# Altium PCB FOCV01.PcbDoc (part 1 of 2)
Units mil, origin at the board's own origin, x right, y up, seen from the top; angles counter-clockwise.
Board outline 3845.03 x 2425.03 mil, 2 copper layers (Top Layer, Bottom Layer); 118 components, 90 nets, 380 pads, 232 vias.
Unrouted connection lines stored in the file: 2.
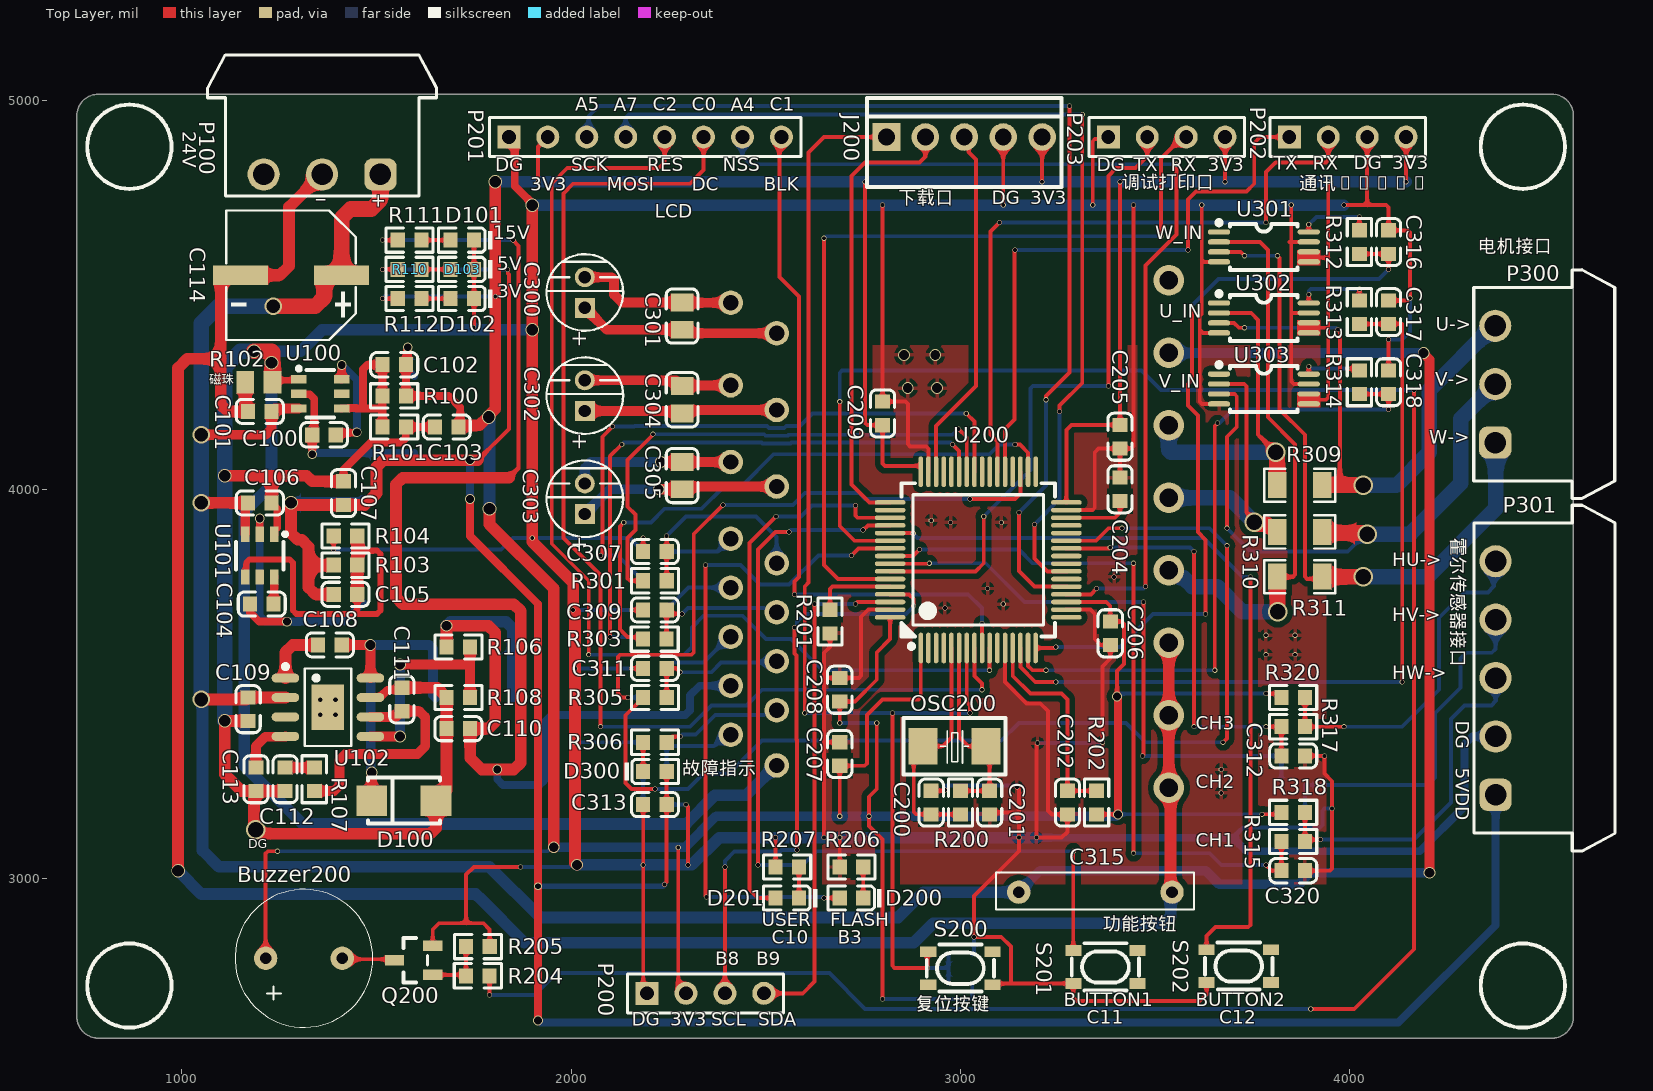
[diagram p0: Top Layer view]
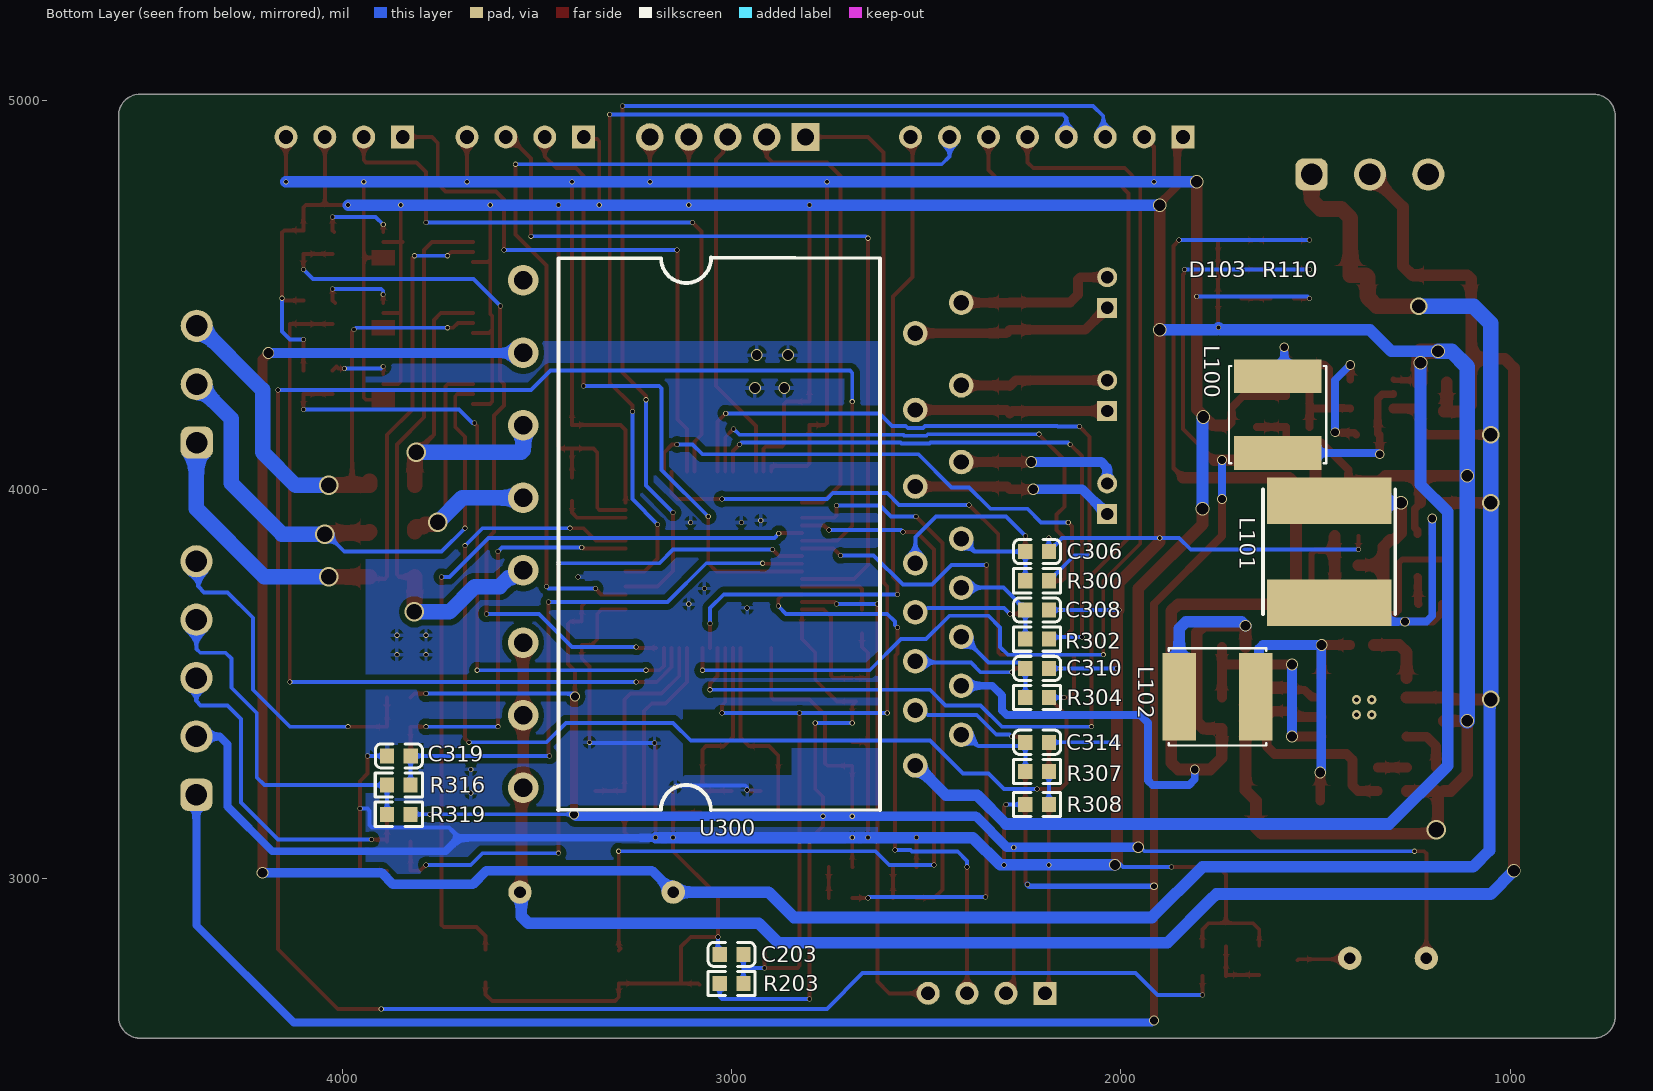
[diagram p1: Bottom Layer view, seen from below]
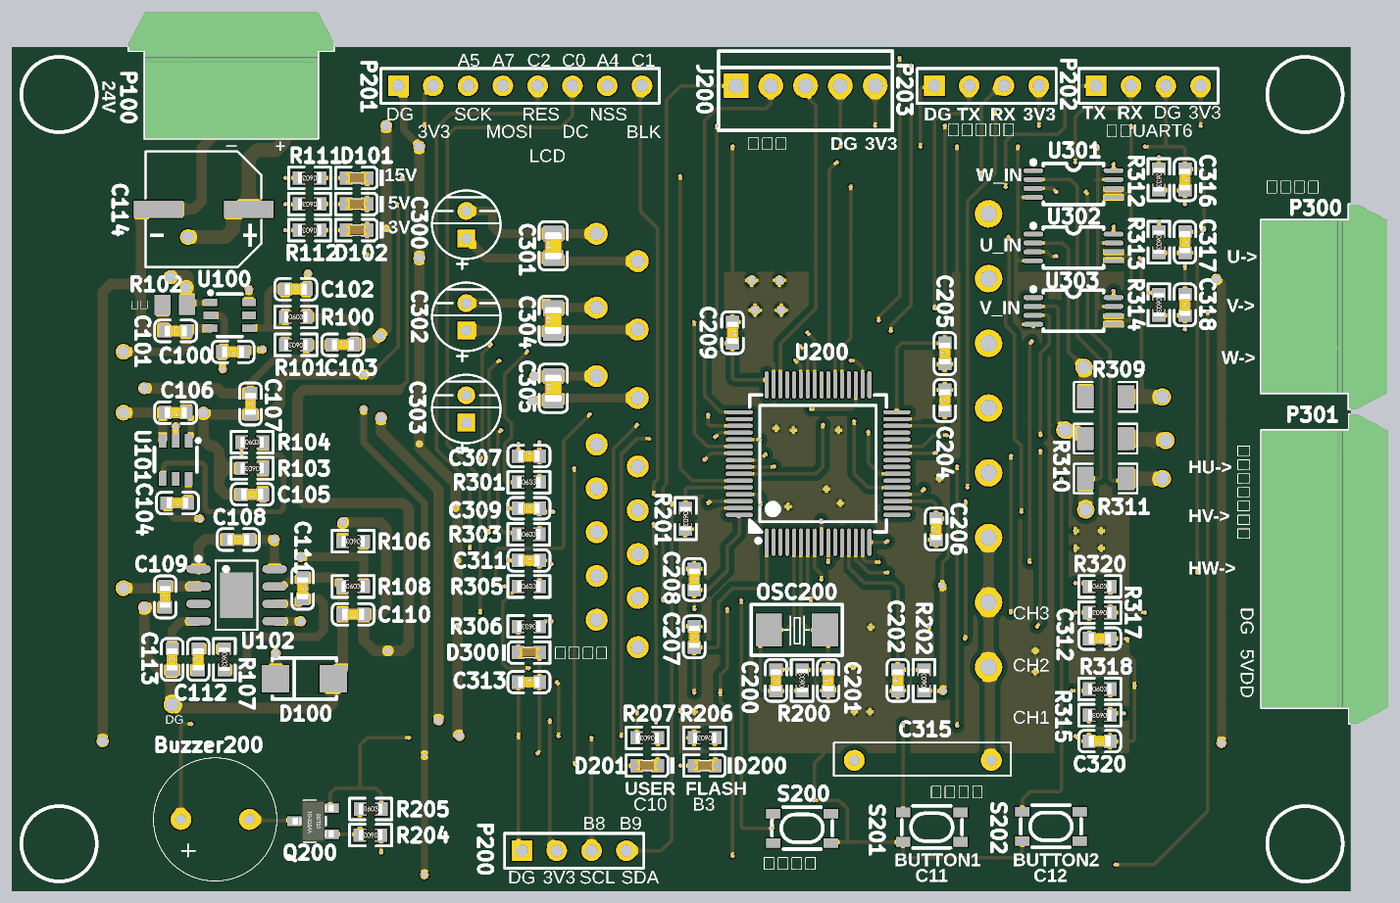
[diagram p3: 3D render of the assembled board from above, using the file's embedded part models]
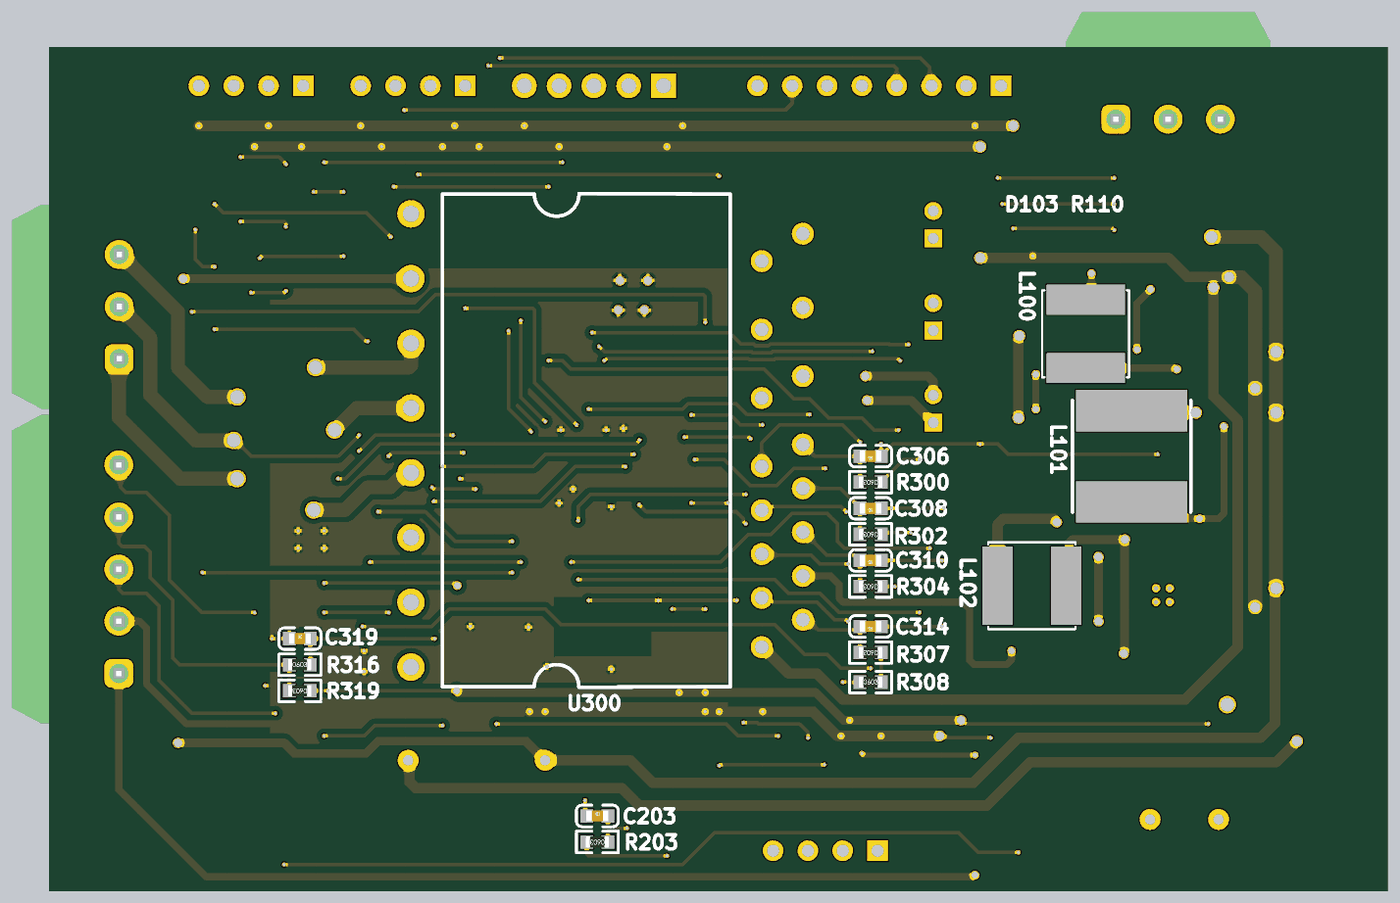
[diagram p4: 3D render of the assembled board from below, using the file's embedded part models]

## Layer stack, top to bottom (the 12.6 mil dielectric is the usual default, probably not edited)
Top Solder: solder mask 0.4, Solder Resist, Dk 3.5
Top Layer: signal copper 1.4
Dielectric 1: dielectric 12.6, FR-4, Dk 4.8
Bottom Layer: signal copper 1.4
Bottom Solder: solder mask 0.4, Solder Resist, Dk 3.5

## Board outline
777.9,2590.44 cw(c785,2645) 730.44,2637.9 cw(c735,2640) 729.98,2640 729.99,4960 cw(c785,4960) 784.97,5015.01 cw(c785,5010) 785,5015.01 4520,5015.02 cw(c4520,4960) 4575.02,4960 cw(c4570,4960) 4575.01,4959.97 4575.01,2645 4575.02,2645 ccw(c4570,2645) 4575.01,2645.03 4575.02,2645 cw(c4520,2645) 4527.1,2590.44 cw(c4525,2595) 4525,2589.99 4520,2589.99 ccw(c4520,2595) 4520,2589.99 ccw(c4520,2645) 4520.01,2589.99 4520,2589.99 785.08,2589.99 cw(c785,2595) 785,2589.98 cw(c785,2645) 784.72,2589.99 780,2589.99 cw(c780,2595)

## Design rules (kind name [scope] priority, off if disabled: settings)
Clearance [All] p1: gap=6 ignorepadtopadclearanceinfootprint=FALSE
HoleToHoleClearance [All] p1: gap=0 allowstackedmicrovias=TRUE
MinimumSolderMaskSliver [All] p1: minsoldermaskwidth=0
PolygonConnect [All] p1: connectstyle=Relief reliefconductorwidth=10 reliefentries=4 polygonreliefangle="90 Angle" airgapwidth=10
RoutingVias [All] p1: holewidth=28 width=50 viastyle="Through Hole" minholewidth=28 minwidth=50 maxholewidth=28 maxwidth=50
SilkToSilkClearance [All] p1: silktosilkclearance=0
SilkToSolderMaskClearance [IsPad] p1: minsilkscreentomaskgap=0 clearancetoexposedcopper=TRUE
SolderMaskExpansion [All] p1: expansion=4 istentingtop=FALSE
Width [All] p1: maxlimit=100 minlimit=10 preferedwidth=10
26 further rules are at their usual default settings.

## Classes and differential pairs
component class 03_Sensor: C300 C301 C302 C303 C304 C305 C306 C307 C308 C309 C310 C311 C312 C313 C314 C315 C316 C317 C318 C319 C320 D300 P300 P301 R300 R301 R302 R303 R304 R305 R306 R307 R308 R309 R310 R311 R312 R313 R314 R315 R316 R317 R318 R319 R320 U300 U301 U302 U303
component class 02_Mcu: Buzzer200 C200 C201 C202 C203 C204 C205 C206 C207 C208 C209 D200 D201 J200 OSC200 P200 P201 P202 P203 Q200 R200 R201 R202 R203 R204 R205 R206 R207 S200 S201 S202 U200
component class 01_Power: C100 C101 C102 C103 C104 C105 C106 C107 C108 C109 C110 C111 C112 C113 C114 D100 D101 D102 D103 L100 L101 L102 P100 R100 R101 R102 R103 R104 R106 R107 R108 R110 R111 R112 U100 U101 U102

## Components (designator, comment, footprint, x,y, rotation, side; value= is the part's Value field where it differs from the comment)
Buzzer200 "Buzzer" buzzer-0905 1313.43,2795 r90 top
C100 "100nF (104) 10% 50V" 0603_C 1365,4140 r180 top
C101 "10uF (106) 10% 50V" 0603_C 1200,4200 r0 top
C102 "56pF (560) 5% 50V" 0603_C 1545.32,4320 r0 top
C103 "22uF (226) 20% 6.3V" 0603_C 1680.32,4160 r0 top
C104 "100nF (104) 10% 50V" 0603_C 1205,3705 r180 top
C105 "56pF (560) 5% 50V" 0603_C 1420,3730 r180 top
C106 "10uF (106) 10% 50V" 0603_C 1200,3965 r180 top
C107 "22uF (226) 20% 6.3V" 0603_C 1415,3990 r270 top
C108 "100nF (104) 10% 50V" 0603_C 1380,3600 r0 top
C109 "10uF (106) 10% 50V" 0603_C 1170,3435 r90 top
C110 "10uF (106) 10% 10V" 0603_C 1710,3385 r180 top
C111 "10pF (100) 5% 50V" 0603_C 1565,3460 r270 top
C112 "1.5pF (1R5) 0.25pF 50V" 0603_C 1265,3255 r90 top
C113 "8.2nF (822) 10% 50V" 0603_C 1190,3255 r90 top
C114 "220UF/35V" CAP_L8.3_W8.3 1280,4550 r180 top
C200 "22pF (220) 5% 50V" 0603_C 2925,3195 r270 top
C201 "22pF (220) 5% 50V" 0603_C 3075,3195 r90 top
C202 "100nF (104) 10% 50V" 0603_C 3275,3195 r90 top
C203 "100nF (104) 10% 50V" 0603_C 3000,2805 r180 bottom
C204 "2.2uF (225) 10% 16V" 0603_C 3410,4000 r90 top
C205 "100nF (104) 10% 50V" LC-0603_C 3410,4135 r90 top
C206 "100nF (104) 10% 50V" LC-0603_C 3385,3630 r90 top
C207 "100nF (104) 10% 50V" LC-0603_C 2690,3320 r270 top
C208 "100nF (104) 10% 50V" LC-0603_C 2690,3485 r270 top
C209 "100nF (104) 10% 50V" LC-0603_C 2800,4195 r270 top
C300 "22UF/35V" 电解电容5*7 2010.03,4500.33 r90 top
C301 "100nF(104) 10% 50V" 0805_C 2285,4445 r90 top
C302 "22UF/35V" 电解电容5*7 2010.03,4235.33 r90 top
C303 "22UF/35V" 电解电容5*7 2010.03,3970.33 r90 top
C304 "100nF(104) 10% 50V" 0805_C 2285,4230 r90 top
C305 "100nF(104) 10% 50V" 0805_C 2285,4035 r90 top
C306 "1nF (102) 10% 50V" 0603_C 2215,3840 r0 bottom
C307 "1nF (102) 10% 50V" 0603_C 2215,3840 r0 top
C308 "1nF (102) 10% 50V" 0603_C 2215,3690 r0 bottom
C309 "1nF (102) 10% 50V" 0603_C 2215,3690 r0 top
C310 "1nF (102) 10% 50V" 0603_C 2215,3540 r0 bottom
C311 "1nF (102) 10% 50V" 0603_C 2215,3540 r0 top
C312 "1nF (102) 10% 50V" 0603_C 3855,3315 r180 top
C313 "1nF (102) 10% 50V" 0603_C 2215,3190 r0 top
C314 "1nF (102) 10% 50V" 0603_C 2215,3350 r0 bottom
C315 "0.1uF(275V,安规电容)" X2_安规电容_10MM 3543.7,2965 r180 top
C316 "2.2nF (222) 10% 50V" 0603_C 4100,4635 r270 top
C317 "2.2nF (222) 10% 50V" 0603_C 4100,4455 r270 top
C318 "2.2nF (222) 10% 50V" 0603_C 4100,4275 r270 top
C319 "1nF (102) 10% 50V" 0603_C 3854.69,3315 r180 bottom
C320 "1nF (102) 10% 50V" 0603_C 3855,3020 r180 top
D100 "SS54" SMA(DO-214AC)_S1 1570,3200 r0 top
D101 "绿灯 0603" 0603_LED_S1 1720,4640 r180 top
D102 "绿灯 0603" 0603_LED_S1 1720,4490 r180 top
D103 "绿灯 0603" 0603_LED_S1 1720,4565 r180 top
D200 "绿灯 0603" 0603_LED_S1 2720,2949.69 r180 top
D201 "绿灯 0603" 0603_LED_S1 2555,2949.69 r180 top
D300 "绿灯 0603" 0603_LED_S1 2215,3275 r0 top
J200 "KF2510-5A" KF2510-5A 3015,4890.83 r0 top
L100 "10uH ±20% 2.5A 58.6mΩ" L_SMD_L6_W6 1598.91,4195 r90 bottom
L101 "15uH ±20% 2.6A 58mΩ" L_SMD_L8_W8 1495,3835 r270 bottom
L102 "10uH ±20% 2.6A 58mΩ" L_SMD_L6_W6 1755,3465 r0 bottom
OSC200 "8MHZ-5032" 8MHZ-5032 2985,3340 r0 top
P100 "Header 3" KF2EDGK-3.81-WI-3P 1360,4935 r180 top
P200 "Header 4" HDR1X4 2195,2705 r0 top
P201 "Header 8" HDR1X8 1840,4905 r0 top
P202 "Header 4" HDR1X4 3845,4905 r0 top
P203 "Header 4" HDR1X4 3380,4905 r0 top
P300 "Header 3" KF2EDGK-3.81-WI-3P 4500,4270 r90 top
P301 "Header 5" KF2EDGK-3.81-WI-5P 4500.98,3515 r90 top
Q200 "SS8050 Y1" SOT-23(SOT-23-3) 1595,2790 r0 top
R100 "100KΩ (1003) ±1%" 0603_R 1545.32,4240 r0 top
R101 "22.1KΩ  ±1%" 0603_R 1545.32,4160 r180 top
R102 "0Ω (0R0) ±1%" LC-0805 1197.5,4275 r0 top
R103 "100KΩ (1003) ±1%" 0603_R 1420,3805 r180 top
R104 "13.7KΩ  ±1%" 0603_R 1420,3880 r0 top
R106 "10.2KΩ" 0603_R 1710,3595 r180 top
R107 "37.4KΩ" 0603_R 1340,3255 r270 top
R108 "576Ω" 0603_R 1710,3465 r0 top
R110 "10KΩ (1002) ±1%" 0603_R 1585,4565 r180 top
R111 "10KΩ (1002) ±1%" 0603_R 1585,4640 r180 top
R112 "10KΩ (1002) ±1%" 0603_R 1585,4490 r180 top
R200 "1MΩ (1004) ±1%" 0603_R 3000,3195 r90 top
R201 "10KΩ (1002) ±1%" 0603_R 2665,3660 r270 top
R202 "0Ω (0R0) ±1%" 0603_R 3350,3195 r90 top
R203 "10KΩ (1002) ±1%" 0603_R 3000,2730 r0 bottom
R204 "1KΩ (1001) ±1%" 0603_R 1760,2750 r180 top
R205 "10KΩ (1002) ±1%" 0603_R 1760.31,2825 r0 top
R206 "10KΩ (1002) ±1%" 0603_R 2720,3029.69 r180 top
R207 "10KΩ (1002) ±1%" 0603_R 2555,3029.68 r180 top
R300 "100Ω (1000) ±1%" 0603_R 2215,3765 r0 bottom
R301 "100Ω (1000) ±1%" 0603_R 2215,3765 r0 top
R302 "100Ω (1000) ±1%" 0603_R 2215,3615 r0 bottom
R303 "100Ω (1000) ±1%" 0603_R 2214.68,3615 r0 top
R304 "100Ω (1000) ±1%" 0603_R 2215,3465 r0 bottom
R305 "100Ω (1000) ±1%" 0603_R 2215,3465 r0 top
R306 "3.6KΩ (3601) ±1%" 0603_R 2215,3350 r180 top
R307 "1.8KΩ (1801) ±1%" 0603_R 2215,3275 r0 bottom
R308 "3KΩ (3001) ±1%" 0603_R 2215,3190 r180 bottom
R309 "0.001Ω" R1206 3895,4005 r0 top
R310 "0.001Ω" R1206 3895,3885 r0 top
R311 "0.001Ω" R1206 3895,3770 r0 top
R312 "22Ω (22R0) ±1%" 0603_R 4025,4635 r270 top
R313 "22Ω (22R0) ±1%" 0603_R 4025,4455 r270 top
R314 "22Ω (22R0) ±1%" 0603_R 4025,4275 r270 top
R315 "1KΩ (1001) ±1%" 0603_R 3855,3095 r180 top
R316 "1KΩ (1001) ±1%" 0603_R 3855,3240 r180 bottom
R317 "1KΩ (1001) ±1%" 0603_R 3855,3390 r180 top
R318 "4.7KΩ (4701) ±1%" 0603_R 3855,3170 r0 top
R319 "4.7KΩ (4701) ±1%" 0603_R 3855,3165 r0 bottom
R320 "4.7KΩ (4701) ±1%" 0603_R 3855,3465 r0 top
S200 "KEY" KEY_WHITE 3000,2770 r180 top
S201 "KEY" KEY_WHITE 3372.68,2773.18 r180 top
S202 "KEY" KEY_WHITE 3715,2775.51 r180 top
U100 "TPS54202DDCR" TPS54202DDCR 1355,4240 r180 top
U101 "TPS54202DDCR" TPS54202DDCR 1195,3830 r90 top
U102 "TPS54332DDAR" TPS54332DDAR 1350.41,3435.3 r270 top
U200 "STM32F401RCT6" STM32F401RCT6 3045.79,3818.63 r0 top
U300 "IGCM15F60GA" IGCM15F60GA 3105,3640 r270 bottom
U301 "INA240_A2" INA240A2PWR 3785,4615 r270 top
U302 "INA240_A2" INA240A2PWR 3785,4432.5 r270 top
U303 "INA240_A2" INA240A2PWR 3785,4250 r270 top

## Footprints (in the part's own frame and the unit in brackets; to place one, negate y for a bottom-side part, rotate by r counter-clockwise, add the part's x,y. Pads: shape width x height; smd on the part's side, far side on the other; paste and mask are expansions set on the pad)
8MHZ-5032 [mm]
  rect 1.9x2.4 smd: 1(-2.05,0) 2(2.05,0)
  silkscreen extent -3.33,-1.85 3.32,1.85
0603_C [mm]
  rect 0.93x0.98 smd: 1(-0.77,0) 2(0.77,0)
  silkscreen extent -1.53,-0.79 1.54,0.79, body extent -0.8,-0.4 0.8,0.4, height 0.3
0603_LED_S1 [mm]
  rect 0.93x0.98 smd: A(0.77,0) K(-0.77,0)
  silkscreen extent -1.97,-0.79 1.54,0.79, body extent -0.8,-0.4 0.8,0.4, height 0.6
0603_R [mm]
  rect 0.93x0.98 smd: 1(-0.77,0) 2(0.77,0)
  silkscreen extent -1.54,-0.79 1.54,0.79, body extent -0.85,-0.4 0.85,0.4, height 0.56
0805_C [mm]
  rect 1.16x1.47 smd: 1(-0.89,0) 2(0.89,0)
  silkscreen extent -1.77,-1.04 1.77,1.04, body extent -1,-0.62 1,0.63, height 0.77
buzzer-0905 [mil]
  round 60 hole 30: 1(0,98.43) 2(0,-98.43)
  silkscreen extent -177,-177 177,177
CAP_L8.3_W8.3 [mm]
  rect 3.61x1.26 smd: 1(-3.295,0) 2(3.295,0)
  silkscreen extent -4.23,-4.23 4.23,4.23
HDR1X4 [mm] "Connector; Header; 4 Position"
  rect 1.5x1.5 hole 0.9: 1(0,0)
  round 1.5 hole 0.9: 2(2.54,0) 3(5.08,0) 4(7.62,0)
  silkscreen extent -1.27,-1.27 8.89,1.27
HDR1X8 [mm] "Connector; Header; 8 Position"
  rect 1.5x1.5 hole 0.9: 1(0,0)
  round 1.5 hole 0.9: 2(2.54,0) 3(5.08,0) 4(7.62,0) 5(10.16,0) 6(12.7,0) 7(15.24,0) 8(17.78,0)
  silkscreen extent -1.27,-1.27 19.05,1.27
IGCM15F60GA [mm]
  round 1.6 hole 1: 1(-21.323,17.662) 2(-19.323,14.662) 3(-15.923,17.662) 4(-14.323,14.662) 5(-10.923,17.662) 6(-9.323,14.662) 7(-5.923,17.662) 8(-4.323,14.662) 9(-2.723,17.662) 10(-1.123,14.662) 11(0.477,17.662) 12(2.077,14.662) 13(3.677,17.662) 14(5.277,14.662) 15(6.877,17.662) 16(8.877,14.662)
  round 2 hole 1.2: 17(10.332,-10.938) 18(5.602,-10.938) 19(0.872,-10.938) 20(-3.858,-10.938) 21(-8.588,-10.938) 22(-13.318,-10.938) 23(-18.048,-10.938) 24(-22.778,-10.938)
  silkscreen extent -24.26,-8.65 11.8,12.36
INA240A2PWR [mil]
  oval 13.9x57.24 smd: 1(-46.03,-120.57) 2(-20.44,-120.57) 3(5.15,-120.57) 4(30.74,-120.57) 5(30.74,109.9) 6(5.15,109.9) 7(-20.44,109.9) 8(-46.03,109.9)
  silkscreen extent -76,-126 51,81
KEY_WHITE [mm]
  rect 1.05x0.7 smd: 1(-2.1,1.088) 2(2.1,1.088) 3(-2.1,-1.062) 4(2.1,-1.062)
  silkscreen extent -2.2,-1.54 2.2,1.54
KF2EDGK-3.81-WI-3P [mm] "Horizontal PCB Header with Plastic Latch, pitch 3.81mm, 03p"
  rrect50% 2.1x2.1 hole 1.4: 1(-3.81,3.2)
  round 2.1 hole 1.4: 2(0,3.2) 3(3.81,3.2)
  silkscreen extent -7.47,-4.6 7.47,4.6, body extent -7.46,-4.6 7.46,4.6, height 7.25
KF2EDGK-3.81-WI-5P [mm] "Horizontal PCB Header with Plastic Latch, pitch 3.81mm, 05p"
  rrect50% 2.1x2.1 hole 1.4: 1(-7.62,3.2)
  round 2.1 hole 1.4: 2(-3.81,3.2) 3(0,3.2) 4(3.81,3.2) 5(7.62,3.2)
  silkscreen extent -11.28,-4.6 11.28,4.6, body extent -11.27,-4.6 11.27,4.6, height 7.25
KF2510-5A [mm]
  round 1.8 hole 1.1: 1(4.953,0.36) 2(2.413,0.36) 3(-0.127,0.36) 4(-2.667,0.36)
  rect 1.8x1.8 hole 1.1: 5(-5.207,0.36)
  silkscreen extent -6.48,-2.9 6.22,2.9
L_SMD_L6_W6 [mm]
  rect 2.2x5.72 smd: 1(-2.583,-0.05) 2(2.417,-0.05)
  silkscreen extent -3.26,-3.23 3.09,3.13
L_SMD_L8_W8 [mm]
  rect 3.024x8.12 smd: 1(3.215,0.762) 2(-3.441,0.762)
  silkscreen extent -4.19,-3.56 3.96,5.08
LC-0603_C [mm]
  rect 0.93x0.98 smd: 1(-0.77,0) 2(0.77,0)
  silkscreen extent -1.54,-0.79 1.54,0.79, body extent -0.8,-0.4 0.8,0.4, height 0.3
LC-0805 [mm]
  rect 1.16x1.47 smd: 1(-0.89,0) 2(0.89,0)
R1206 [mil]
  rect 47.54x66.97 smd: 1(-81.22,5.48) 2(35.22,5.48)
  silkscreen extent -114,-37 68,48
SMA(DO-214AC)_S1 [mm]
  rect 2x2 smd: 1(2.1,0) 2(-2.1,0)
  silkscreen extent -2.35,-1.5 2.35,1.5
SOT-23(SOT-23-3) [mm]
  rect 1.25x0.7 smd: 1(1.25,-0.95) 2(1.25,0.95) 3(-1.25,0)
  silkscreen extent -0.65,-1.46 0.9,1.46, body extent -1.5,-1.5 1.5,1.5, height 1.3
STM32F401RCT6 [mm]
  oval 0.3x2 smd: 1(-3.75,-5.75) 2(-3.25,-5.75) 3(-2.75,-5.75) 4(-2.25,-5.75) 5(-1.75,-5.75) 6(-1.25,-5.75) 7(-0.75,-5.75) 8(-0.25,-5.75) 9(0.25,-5.75) 10(0.75,-5.75) 11(1.25,-5.75) 12(1.75,-5.75) 13(2.25,-5.75) 14(2.75,-5.75) 15(3.25,-5.75) 16(3.75,-5.75) 33(3.75,5.75) 34(3.25,5.75) 35(2.75,5.75) 36(2.25,5.75) 37(1.75,5.75) 38(1.25,5.75) 39(0.75,5.75) 40(0.25,5.75) 41(-0.25,5.75) 42(-0.75,5.75) 43(-1.25,5.75) 44(-1.75,5.75) 45(-2.25,5.75) 46(-2.75,5.75) 47(-3.25,5.75) 48(-3.75,5.75)
  oval 2x0.3 smd: 17(5.75,-3.75) 18(5.75,-3.25) 19(5.75,-2.75) 20(5.75,-2.25) 21(5.75,-1.75) 22(5.75,-1.25) 23(5.75,-0.75) 24(5.75,-0.25) 25(5.75,0.25) 26(5.75,0.75) 27(5.75,1.25) 28(5.75,1.75) 29(5.75,2.25) 30(5.75,2.75) 31(5.75,3.25) 32(5.75,3.75) 49(-5.75,3.75) 50(-5.75,3.25) 51(-5.75,2.75) 52(-5.75,2.25) 53(-5.75,1.75) 54(-5.75,1.25) 55(-5.75,0.75) 56(-5.75,0.25) 57(-5.75,-0.25) 58(-5.75,-0.75) 59(-5.75,-1.25) 60(-5.75,-1.75) 61(-5.75,-2.25) 62(-5.75,-2.75) 63(-5.75,-3.25) 64(-5.75,-3.75)
  silkscreen extent -5,-5.79 5,5
TPS54202DDCR [mm]
  rect 1x0.55 smd: 1(1.393,-1.077) 2(1.393,-0.127) 3(1.393,0.823) 4(-1.408,0.823) 5(-1.408,-0.127) 6(-1.408,-1.077)
  silkscreen extent -0.91,-1.9 1.52,1.42
TPS54332DDAR [mm]
  oval 0.6x1.8 smd: 1(-2.024,-2.148) 2(-0.754,-2.148) 3(0.516,-2.148) 4(1.786,-2.148) 5(1.786,3.397) 6(0.516,3.397) 7(-0.754,3.397) 8(-2.024,3.397)
  rect 3x2.13 smd: 9(-0.119,0.625)
  silkscreen extent -2.92,-2.3 2.41,2.15
X2_安规电容_10MM [mil]
  round 60 hole 30: 1(0,0) 2(393.7,0)
  silkscreen extent -57,-51 452,44
电解电容5*7 [mm]
  rect 1.3x1.3 hole 0.8: 1(-0.865,-0.634)
  round 1.3 hole 0.8: 2(1.135,-0.634)
  silkscreen extent -2.36,-3.13 2.63,1.87

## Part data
C100 C104 C108 C202 C203 C205 C206 C207 C208 C209 C315: library part "0603 100nF (104) 10% 50V", "贴片电容", Package=0603, SuppliersPartNumber=C14663
C101 C106 C109 C110: library part "0603 10uF (106) 10% 10V", "贴片电容", Package=0603, SuppliersPartNumber=C19702
C102 C105: library part "0603 56pF (560) 5% 50V", "贴片电容", Package=0603, SuppliersPartNumber=C39148
C103 C107: library part "0603 22uF (226) 20% 6.3V", "贴片电容", Package=0603, SuppliersPartNumber=C59461
C111: library part "0603 10pF (100) 5% 50V", "贴片电容", Package=0603, SuppliersPartNumber=C1634
C112: library part "0603 1.5pF (1R5) 0.25pF 50V", "贴片电容", Package=0603, SuppliersPartNumber=C1639
C113: library part "0603 8.2nF (822) 10% 50V", "贴片电容", Package=0603, SuppliersPartNumber=C27920
C114 C300 C302 C303: library part CAP2, "电解电容"
C200 C201: library part "0603 22pF (220) 5% 50V", "贴片电容", Package=0603, SuppliersPartNumber=C1653
C204: library part "0603 2.2uF (225) 10% 16V", "贴片电容", Package=0603, SuppliersPartNumber=C23630
C301 C304 C305: library part "0805 100nF(104) 10% 50V", "贴片电容", Package=0805, SuppliersPartNumber=C49678
C306 C307 C308 C309 C310 C311 C312 C313 C314 C319 C320: library part "0603 1nF (102) 10% 50V", "贴片电容", Package=0603, SuppliersPartNumber=C1588
C316 C317 C318: library part "0603 2.2nF (222) 10% 50V", "贴片电容", Package=0603, SuppliersPartNumber=C1604
D100: library part "SMA(DO-214AC) SS54", "二极管", Package=SMA(DO-214AC), SuppliersPartNumber=C22452
D101 D102 D103 D200 D201 D300: library part "0603 绿灯", "发光二极管", Package=0603, SuppliersPartNumber=C72043
L100 L101 L102: library part L
P100 P300: "Header, 3-Pin"
P200 P202 P203: "Header, 4-Pin"
P201: "Header, 8-Pin"
P301: "Header, 5-Pin"
Q200: library part "SOT-23 SS8050 Y1", "三极管", Package=SOT-23, SuppliersPartNumber=C2150
R100 R101 R103 R104: library part "0603 100KΩ (1003) 1%", "贴片电阻", Package=0603, SuppliersPartNumber=C25803
R102 R202: library part "0603 0Ω (0R0) 1%", "贴片电阻", Package=0603, SuppliersPartNumber=C21189
R106 R107 R108 R110 R111 R112 R201 R203 R205 R206 R207: library part "0603 10KΩ (1002) 1%", "贴片电阻", Package=0603, SuppliersPartNumber=C25804
R200: library part "0603 1MΩ (1004) 1%", "贴片电阻", Package=0603, SuppliersPartNumber=C22935
R204 R315 R316 R317: library part "0603 1KΩ (1001) 1%", "贴片电阻", Package=0603, SuppliersPartNumber=C21190
R300 R301 R302 R303 R304 R305: library part "0603 100Ω (1000) 1%", "贴片电阻", Package=0603, SuppliersPartNumber=C22775
R306: library part "0603 3.6KΩ (3601) 1%", "贴片电阻", Package=0603, SuppliersPartNumber=C22980
R307: library part "0603 1.8KΩ (1801) 1%", "贴片电阻", Package=0603, SuppliersPartNumber=C4177
R308: library part "0603 3KΩ (3001) 1%", "贴片电阻", Package=0603, SuppliersPartNumber=C4211
R309 R310 R311: library part "0805 10KΩ (1002) 1%", "贴片电阻", Package=0805, SuppliersPartNumber=C17414
R312 R313 R314: library part "0603 22Ω (22R0) 1%", "贴片电阻", Package=0603, SuppliersPartNumber=C23345
R318 R319 R320: library part "0603 4.7KΩ (4701) 1%", "贴片电阻", Package=0603, SuppliersPartNumber=C23162
S200 S201 S202: "白色方块"

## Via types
v1: diameter 13, hole 10, Top Layer to Bottom Layer, 174 vias
v2: diameter 30, hole 25, Top Layer to Bottom Layer, 15 vias
v3: diameter 25, hole 20, Top Layer to Bottom Layer, 12 vias
v4: diameter 35, hole 30, Top Layer to Bottom Layer, 11 vias
v5: diameter 24, hole 12, Top Layer to Bottom Layer, 8 vias
v6: diameter 50, hole 40, Top Layer to Bottom Layer, 7 vias
v7: diameter 45, hole 35, Top Layer to Bottom Layer, 4 vias
v8: diameter 20, hole 15, Top Layer to Bottom Layer, 1 vias

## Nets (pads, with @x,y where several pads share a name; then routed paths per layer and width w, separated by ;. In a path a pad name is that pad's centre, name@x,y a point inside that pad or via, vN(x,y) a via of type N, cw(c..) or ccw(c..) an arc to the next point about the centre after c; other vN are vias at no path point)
3V3DD: Buzzer200.1 C102.2 C103.2 C205.2 C206.2 C207.2 C208.2 C209.2 J200.1 L100.2 P200.2 P201.2 P202.4 P203.4 R100.2 R112.2 R202.1 R203.2 R318.1 R319.1 R320.1 U200.1 U200.19 U200.32 U200.48 U200.64 U301.5 U301.6 U302.5 U302.6 U303.5 U303.6 | length 14543
  Top Layer w10: Buzzer200.1@1215,2795 1215,3064.14 1220.86,3070 v1(1245,3070) ; v1(1515,4490) R112.2@1554.68,4490 ; v1(1915,4790) 1915,4880 P201.2@1940,4905 ; v1(2275,3080) 2275,2725 P200.2@2295,2705 ; v1(2690,3160) C207.2@2690,3289.69 2754.14,3289.68 2760,3295.54 2760,3420 2800,3460 2892.29,3460 2898.15,3465.86 U200.1@2898.15,3592.25 ; v1(2690,3400) 2690,3444.68 2680,3454.68 2729.14,3454.68 2785,3510.54 2785,3580.58 2819.42,3615 U200.64@2819.42,3670.99 ; v1@2755,4787.71 2755,4170.54 2760.86,4164.69 C209.2@2800,4164.69 2800,4065.86 2805.86,4060 2897.31,4060 2898.15,4059.16 U200.48@2898.15,4045 ; v1(2785,3400) 2785,3230 2765,3210 v1(2765,3160) 2765,3135 2800,3100 v1(2800,2690) ; v1(3210,4790) J200.1@3210,4905 ; U200.19@3272.16,3710.36 3374.64,3710.36 3385,3700 C206.2@3385,3660.31 ; U200.32@3272.16,3966.27 3272.16,4152.16 3285.31,4165.31 C205.2@3410,4165.31 v1(3410,4790) ; R202.1@3350,3164.69 v3(3404.69,3164.69) ; C206.2@3390,3660.31 3414.14,3660.31 3420,3654.46 3420,3551 3402.41,3533.41 v3(3402.41,3467.41) ; v1(3680,4790) P203.4@3680,4905 ; v1(3775,3165) 3819.69,3165 R318.1@3824.69,3170 ; v1(3785,3475) 3814.69,3475 R320.1@3824.69,3465 ; 3895,4230 3939.14,4230 3945,4235.86 3945,4415.43 ; 3895,4415 3944.57,4415 3945,4415.43 ; 3895,4595 3945,4595 ; v1(3945,4790) 3945,4595 ; v1(4145,4790) P202.4@4145,4905 ; 3945,4415.43 3945,4595
  Top Layer w20: v3(1580,4365) 1579.04,4364.04 1579.04,4323.41 C102.2@1575.63,4320 R100.2@1575.63,4240 1640,4240 1685,4240 1715,4210 1715,4171.3 C103.2@1725.32,4160.98 ; v3(3402.41,3467.41) 3404.69,3465.13 v3(3404.69,3164.69)
  Top Layer w30: C103.2@1728.62,4164.29 1764.29,4164.29 1785.68,4185.68 v4(1787.84,4185.68) 1787.84,4189.19 1805,4206.35 v1(1805,4495) v4(1805,4790) ; v4(1790,3950) 1790,3910 1955,3745 v2(1955,3080)
  Bottom Layer w10: v1(1245,3070) 1939.59,3070 1949.59,3080 v2(1955,3080) ; v1(1515,4490) 1520,4495 v1(1805,4495) ; v1(2690,3400) v1(2785,3400) ; v1(2800,2690) 3024.46,2690 3030.32,2695.86 R203.2@3030.32,2730 ; v3(3402.41,3467.41) 3403.17,3467.41 3410.77,3475 v1(3785,3475) ; v3(3404.69,3164.69) 3405,3165 v1(3775,3165) R319.1@3824.69,3165
  Bottom Layer w20: v3(1580,4365) 1580,4307.1 L100.2@1596.95,4290.15
  Bottom Layer w25: v2(1955,3080) v1(2275,3080) 2292.62,3080 2372.62,3160 v1(2690,3160) v1(2765,3160) 3400,3160 v3(3404.69,3164.69)
  Bottom Layer w30: v4(1787.84,4185.68) 1790,4183.51 v4(1790,3950) ; v4(1805,4790) v1(1915,4790) v1(2755,4790) v1(3210,4790) v1(3410,4790) v1(3680,4790) v1(4145,4790)
3V3DDA: C202.2 R202.2 U200.13 | length 547.1
  Top Layer w10: U200.13@3134.37,3592.25 3134.37,3520.63 3180,3475 3260,3475 3275,3460 C202.2@3275,3225.32 3315,3225.32 R202.2@3350,3225.32
5VDD: C105.2 C107.2 C313.2 D300.A L101.2 P301.1 R103.2 R110.2 | length 7053.6
  Top Layer w10: v1(1515,4565) R110.2@1554.68,4565 ; 1760,4075 1840,4155 1840,4551.69 1837.07,4554.61 1837.07,4564.43 v1(1836.5,4565) ; v1(2240,2985) 2240,2985.81 2245.31,2991.13 C313.2@2245.31,3190 D300.A@2245.32,3275
  Top Layer w20: v3(1740,3975) 1740,3880 1915,3705 v8(1915,2980) v3(1915,2635)
  Top Layer w30: C105.2@1389.68,3730 1342.57,3730 1325,3747.57 1325,3805 ; R103.2@1389.68,3805 1325,3805 ; 1760,4075 v3(1740,4075) 1517.57,4075 1500,4057.43 1500,3989.69 1470,3959.69 C107.2@1415,3959.69 1286.67,3959.69 1281.35,3965 v4(1280,3965) 1280,3887.57 1297.57,3870 1307.43,3870 1325,3852.43 1325,3805
  Bottom Layer w10: v1(1515,4565) v1(1836.5,4565)
  Bottom Layer w15: v8(1915,2980) 2235,2980 v1(2240,2985)
  Bottom Layer w20: v3(1740,3975) v3(1740,4075) ; v3(1915,2635) 1916.35,2635 1921.35,2630 4125,2630 4375,2880 P301.1@4375,3215
  Bottom Layer w30: v4(1280,3965) 1459.53,3965 L101.2@1465,3970.47
15VDD: C110.1 L102.2 R106.2 R111.2 U300.13 | length 4229.9
  Top Layer w10: v1(1515,4640) 1553.77,4640 1554.23,4640.46 R111.2@1554.68,4640 ; 1840,4030 1865,4055 1865,4625 v1(1850,4640)
  Top Layer w30: R106.2@1679.68,3595 v2(1679.68,3649.68) 1787.43,3649.68 1805,3632.11 1805,3402.57 1787.43,3385 C110.1@1740.31,3385 1740.31,3309.69 1770,3280 v3(1810,3280) 1852.43,3280 1870,3297.57 1870,3687.43 1852.43,3705 1567.57,3705 1550,3722.57 1550,4012.43 1567.57,4030 1840,4030
  Bottom Layer w10: v1(1515,4640) v1(1850,4640)
  Bottom Layer w20: v3(1810,3280) 1810,3255 1825,3240 1918.28,3240 1930,3251.72 1930,3400 1950,3420 2293.28,3420 2305,3431.72 2305,3470 2330.23,3495.23 U300.13@2409.65,3495.23
  Bottom Layer w30: v2(1679.68,3649.68) 1690,3660 1832.58,3660 1850.15,3642.43 L102.2@1850.15,3466.95
24V: C101.2 C106.2 C109.2 C114.1 C315.2 P100.1 U100.3 U101.3 U102.2 U300.23 | length 8148.5
  Top Layer w25: v7(1050,4140) 1215,4140 1230.31,4155.31 C101.2@1230.31,4200 1230.31,4200.98 1236.93,4207.6 U100.3@1300.17,4207.6 ; U101.3@1162.6,3884.83 1162.6,3956.93 1169.69,3964.02 C106.2@1169.69,3965 ; v2(4190,4350) 4190,4348.65 4205,4333.65 v2(4205,3015)
  Top Layer w30: v7(1050,3460) 1164.69,3460 C109.2@1170,3465.31 1170.16,3465.16 1265.69,3465.16 U102.2@1265.85,3465 ; v7(1050,3965) C106.2@1169.69,3965
  Top Layer w40: v7@1236.74,4470 1342.14,4470 1365.57,4493.43 1365.57,4545.2 1370.38,4550 C114.1@1409.72,4550 1410,4550.28 1410,4696.57 1433.43,4720 1486.57,4720 1510,4743.43 P100.1@1510,4809.02
  Bottom Layer w25: C315.2@3150,2965 3205,3020 3630,3020 3665,2985 3870,2985 3900,3015 v2(4205,3015) ; U300.23@3535.63,4350.55 3536.18,4350 v2(4190,4350)
  Bottom Layer w30: v7(1050,3460) 1052.87,3457.13 1052.87,3072.13 1095,3030 1790,3030 1920,2900 2840,2900 2905,2965 C315.2@3150,2965
  Bottom Layer w40: v7(1050,3460) v7(1050,3965) v7(1050,4140) 1050,4426.57 1093.43,4470 v7(1235,4470)
24VGND: C101.1 C114.2 C315.1 P100.2 R102.1 U300.17 U300.18 U300.19 | length 5711.6
  Top Layer w30: v4(990,3020) 990,4311.57 1013.43,4335 1100,4335 ; R102.1@1162.46,4275 1162.46,4208.2 1169.69,4200.98 C101.1@1169.69,4200 1117.57,4200 1100,4217.57 1100,4335 ; P100.2@1360,4809.02 1359.02,4809.02 1275,4725 1275,4573.43 1251.57,4550 C114.2@1150.28,4550 1109.8,4550 1100,4540.2 1100,4335 ; U300.19@3535.63,3605.67 U300.18@3535.63,3419.45 U300.17@3535.63,3233.22 3539.87,3228.98 3539.87,2968.83 C315.1@3543.7,2965
  Bottom Layer w30: v4(990,3020) 1050,2960 1755,2960 1769.99,2945.01 1880,2835 2880,2835 2930,2885 3522.43,2885 3540,2902.57 3540,2961.3 C315.1@3543.7,2965
ADC1_IN0: C317.2 R313.2 U200.14 | length 2075.9
  Top Layer w10: U200.14@3154.06,3592.25 3154.06,3543.31 3192.37,3505 v1(3245,3505) ; R313.2@4025,4424.68 C317.2@4100,4424.69 4100.31,4425 4135,4425 v1(4135,3505)
  Bottom Layer w10: v1(3245,3505) v1(4135,3505)
ADC1_IN1: C318.2 R314.2 U200.15 | length 1737.3
  Top Layer w10: U200.15@3173.74,3592.25 3174.09,3591.91 3174.09,3545.91 3185,3535 v1(3220,3535) ; v1(3653.5,3535) 3653.5,4162.69 3660,4169.19 v1(3660,4170) ; R314.2@4025,4244.68 C318.2@4100,4244.69 v1(4100,4205)
  Bottom Layer w10: v1(3220,3535) v1(3653.5,3535) ; v1(3660,4170) 3660.57,4170.57 3665.57,4170.57 3700,4205 v1(4100,4205)
ADC1_IN2: C316.2 R312.2 U200.16 | length 1946.8
  Top Layer w10: U200.16@3193.43,3592.25 3242.25,3592.25 v1(3245,3595) ; v1(3593.75,4470.44) 3595,4469.19 3595,4280 3585,4270 3585,4215 3610,4190 3610,3890 3630,3870 v1(3630,3680) ; R312.2@4025,4604.68 C316.2@4100,4604.69 v1(4100,4565)
  Bottom Layer w10: v1(3245,3595) 3410,3595 3495,3680 v1(3630,3680) ; v1(3593.75,4470.44) 3663.31,4540 4075,4540 v1(4100,4565)
BUTTON1: S201.4 U200.52 | length 2258.9
  Top Layer w10: v1(2480,3035) 2480,3845 2525,3890 v1(2560,3890) ; v1(2750,3895) 2762.21,3907.21 U200.52@2819.42,3907.21 ; S201.4@3290,2815 3285,2820 3290,2825 v1(3290,3070)
  Bottom Layer w10: v1@2479.91,3035 2595,3035 2630,3070 v1(3290,3070) ; v1(2560,3890) 2565,3895 v1(2750,3895)
BUTTON2: S202.4 U200.53 | length 2025.8
  Top Layer w10: U200.53@2819.42,3887.53 2877.47,3887.53 v1(2878.74,3886.26) ; S202.4@3632.32,2817.33 3632.32,2852.32 3655,2875 3739.14,2875 3745,2880.86 v1(3745,3775)
  Bottom Layer w10: v1(2878.74,3886.26) 2890,3875 3625,3875 3725,3775 v1(3745,3775)
BUZZER: R204.1 U200.54 | length 6023.3
  Top Layer w10: v1@1790,2700 v1(1790.31,2700.31) R204.1@1790.31,2750 ; v1(2690,4225) 2690,3905.44 2727.6,3867.84 U200.54@2819.42,3867.84 ; v1(3900,2665) 4011.78,2665 4165,2818.22 v1(4165,4255)
  Bottom Layer w10: v1(1790.31,2700.31) 1905.65,2700.31 1962.16,2756.83 2663.17,2756.83 2755,2665 v1(3900,2665) ; v1(2690,4225) 2690,4299.14 2695.86,4305 3465,4305 3515,4255 v1(4165,4255)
